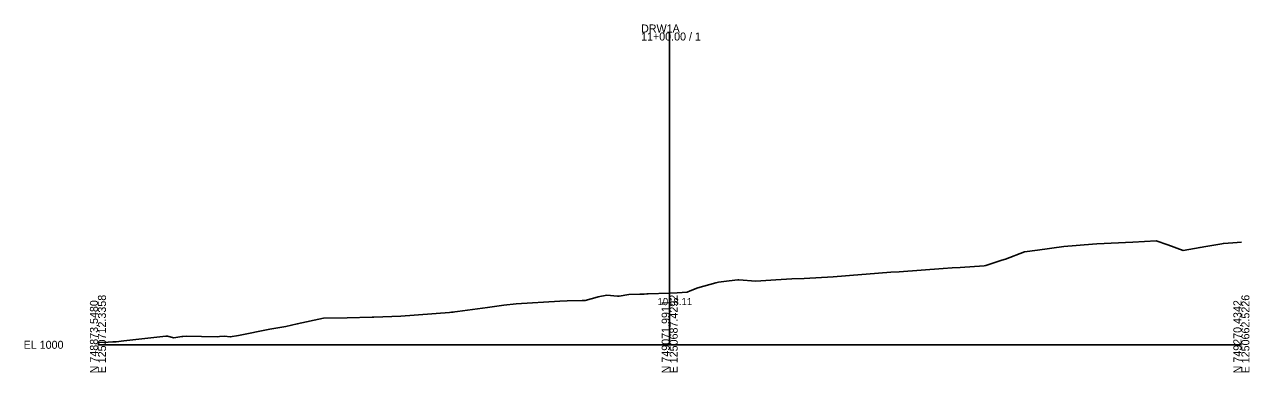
# Model space of a CAD drawing. Extents: x -26 to 403, y -376 to 1112.
# Drawn here: x -25.7 to 402.8, y 990.3 to 1112 of the extents above; entities that cross this region are included whole.
import ezdxf

# ---------------------------------------------------------------- set-up
doc = ezdxf.new("R2010")
doc.units = 0
for name, color, linetype in [('Default', 7, 'Continuous'), ('Exist Cross Section Cell', 7, 'Continuous'), ('Exist XS Center Line Elevation Label', 7, 'Continuous'), ('Exist XS Ground Line', 7, 'Continuous')]:
    doc.layers.add(name, color=color, linetype=linetype)

msp = doc.modelspace()

# ---------------------------------------------------------------- linework, layer by layer
at = {"layer": 'Exist Cross Section Cell'}
for p, q in [((200, 1000), (200, 1109.23)), ((0, 1000), (200, 1000)), ((200, 1000), (400, 1000))]:
    msp.add_line(p, q, dxfattribs=at)
at = {"layer": 'Exist XS Ground Line'}
msp.add_lwpolyline([(0, 1000.76), (3.63, 1000.92), (5.2, 1000.99), (6.42, 1001.06), (9.1, 1001.41), (23.75, 1003.01), (24.28, 1002.97), (26.53, 1002.49), (29.33, 1002.86), (29.7, 1002.92), (30.83, 1003.06), (36.23, 1002.94), (41.65, 1002.82), (42.48, 1002.9), (44.32, 1003.05), (46.27, 1002.74), (49.16, 1003.27), (60.15, 1005.49), (65.68, 1006.41), (69.75, 1007.28), (78.95, 1009.28), (87.17, 1009.43), (95.92, 1009.62), (96.46, 1009.64), (106, 1009.96), (122.93, 1011.34), (123.63, 1011.4), (124.22, 1011.44), (124.83, 1011.53), (125.77, 1011.66), (136.24, 1013.08), (141.94, 1013.83), (146.32, 1014.38), (161.63, 1015.27), (164.12, 1015.41), (169.37, 1015.47), (170.39, 1015.49), (174.64, 1016.62), (174.99, 1016.76), (177.98, 1017.3), (181.75, 1017.03), (182.29, 1017.06), (185.71, 1017.55), (189.57, 1017.71), (189.95, 1017.72), (191.08, 1017.75), (191.98, 1017.79), (192.49, 1017.81), (199.81, 1018.1), (202.61, 1018.2), (206.1, 1018.35), (207.18, 1018.86), (209.91, 1019.96), (216.12, 1021.66), (217.11, 1021.94), (220.79, 1022.37), (223.87, 1022.75), (224.18, 1022.71), (230.16, 1022.24), (237.16, 1022.71), (242.74, 1023.06), (247.11, 1023.18), (257.21, 1023.76), (267.27, 1024.59), (268.74, 1024.71), (277.35, 1025.37), (280.26, 1025.55), (295.67, 1026.69), (298.85, 1026.93), (301.64, 1027.08), (310.04, 1027.62), (310.6, 1027.71), (315.86, 1029.43), (316.99, 1029.8), (317.47, 1029.94), (324.18, 1032.47), (328.63, 1033.04), (337.89, 1034.35), (347.91, 1035.23), (349.42, 1035.34), (362.03, 1035.93), (370.2, 1036.41), (374.23, 1034.99), (379.6, 1033.02), (385.53, 1034.04), (387.56, 1034.37), (393.16, 1035.35), (393.72, 1035.45), (397.04, 1035.69), (400, 1035.92)], dxfattribs=at)

# ---------------------------------------------------------------- texts
at = {"layer": 'Default'}
msp.add_text('-', height=0.0001, dxfattribs=at).set_placement((0, 1000))
at = {"layer": 'Exist Cross Section Cell'}
for s, p in [('DRW1A', (190, 1109.23)), ('11+00.00 / 1', (190, 1106.43)), ('EL 1000', (-26, 998.6))]:
    msp.add_text(s, height=2.8, dxfattribs=at).set_placement(p)
for s, p in [('E 1250712.3358', (2.8, 990)), ('E 1250687.4292', (202.8, 990)), ('E 1250662.5226', (402.8, 990)), ('N 748873.5480', (0, 990)), ('N 749071.9911', (200, 990)), ('N 749270.4342', (400, 990))]:
    msp.add_text(s, height=2.8, rotation=90, dxfattribs=at).set_placement(p)
at = {"layer": 'Exist XS Center Line Elevation Label'}
msp.add_text('1018.11', height=2.5, dxfattribs=at).set_placement((195.77, 1013.86))

doc.saveas('drawing.dxf')
